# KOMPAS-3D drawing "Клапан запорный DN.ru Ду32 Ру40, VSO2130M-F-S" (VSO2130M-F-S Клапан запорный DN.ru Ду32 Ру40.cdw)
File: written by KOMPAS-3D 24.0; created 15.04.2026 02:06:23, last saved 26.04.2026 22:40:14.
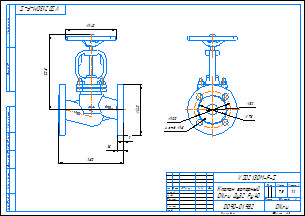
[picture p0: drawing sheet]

Document properties: Автор: DN.ru; Форматы листов документа: A3; Полное имя файла: VSO2130M-F-S Клапан запорный DN.ru Ду32 Ру40.m3d; Масса: 7.5; Наименование: Клапан запорный DN.ru Ду32 Ру40; Количество листов документа: 1; Примечание: D090-01982

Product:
- Part/product: Клапан запорный DN.ru Ду32 Ру40  | designation VSO2130M-F-S
    Масса: 7.5
    Раздел спецификации: Прочие изделия
    Примечание: D090-01982

Views: Вид 1, Вид:1, Проекционный вид 2
Referenced files in C:\Работа\VSO2130M-F-S Клапан запорный DN.ru\DN15\: VSO2130M-F-S DN15 PN40  Клапан запорный сильфонный DN.ru.m3d
Referenced files in C:\Работа\VSO2130M-F-S Клапан запорный DN.ru Ду-x Ру40\DN32\: VSO2130M-F-S Клапан запорный DN.ru Ду32 Ру40.m3d
Referenced files in C:\Program Files\ASCON\KOMPAS-3D v24\Templates\: Чертеж_DN.ru.cdt
Referenced files in C:\Работа\ГОТОВЫЕ ИСХОДНИКИ\VSO2130M-F-S Клапан запорный сальниковый DN.ru Ду15-100 Ру40\DN32\: VSO2130M-F-S Клапан запорный DN.ru Ду32 Ру40.m3d
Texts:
  VSO2130M-F-S
  Чертеж_DN.ru.cdt
  Клапан запорный
  DN.ru Ду32 Ру40
  Клапан запорный DN.ru Ду32 Ру40
  VSO2130M-F-S Клапан запорный DN.ru Ду32 Ру40
Dimensions and other numbers on the sheet: 0; 3; 2; 4; 140; 18; 208; 180; 5; 32; 78; 100; 4 отв.; 1:2; 1; 7,5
